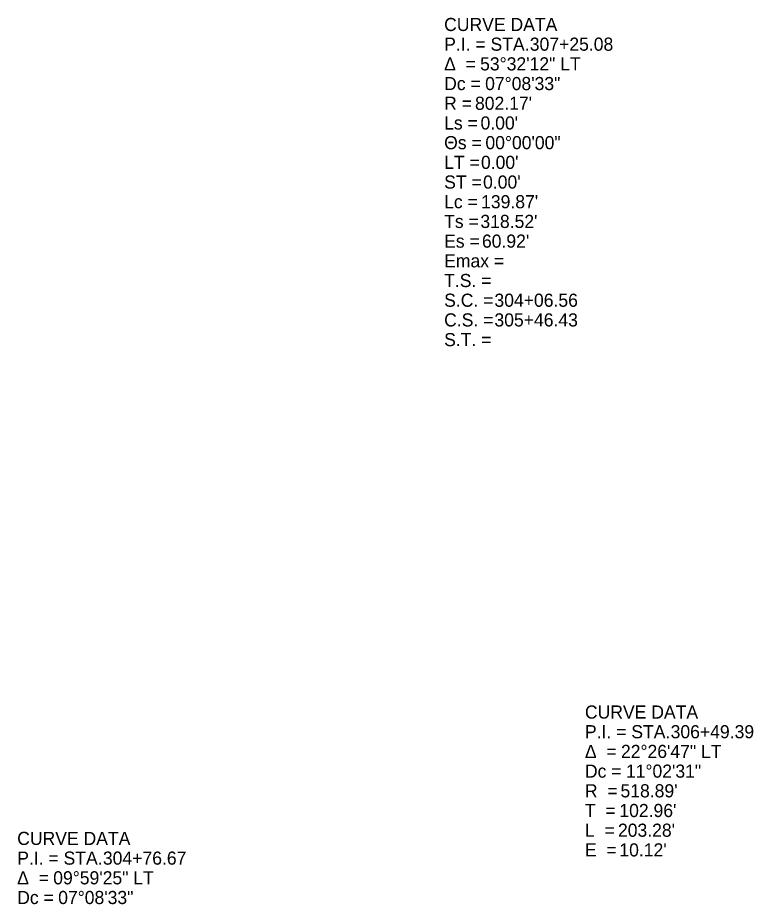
# Model space of a CAD drawing. Extents: x 153902 to 157473, y 413085 to 414252.
# Drawn here: x 154246.5 to 154403.4, y 413877.8 to 414066.9 of the extents above; entities that cross this region are included whole.
import ezdxf

# ---------------------------------------------------------------- set-up
doc = ezdxf.new("R2010")
doc.units = 0
doc.layers.add('GE_P_Alignment_100_Distances', color=7, linetype='Continuous')

msp = doc.modelspace()

# ---------------------------------------------------------------- texts
at = {"layer": 'GE_P_Alignment_100_Distances'}
for s, p in [('CURVE DATA', (154337.45, 414064.06)), ('P.I. = STA. ', (154337.45, 414059.86)), ('307+25.08', (154355.71, 414059.86)), ('Δ  = ', (154337.45, 414055.66)), ('53°32\'12" LT', (154345.12, 414055.66)), ('Dc = ', (154337.45, 414051.46)), ('07°08\'33"', (154346.19, 414051.46)), ('R = ', (154337.45, 414047.26)), ("802.17'", (154344.03, 414047.26)), ('Ls = ', (154337.45, 414043.06)), ("0.00'", (154345.21, 414043.06)), ('Θs = ', (154337.45, 414038.86)), ('00°00\'00"', (154346.25, 414038.86)), ('LT = ', (154337.45, 414034.66)), ("0.00'", (154345.3, 414034.66)), ('ST = ', (154337.45, 414030.46)), ("0.00'", (154345.75, 414030.46)), ('Lc = ', (154337.45, 414026.26)), ("139.87'", (154345.33, 414026.26)), ('Ts = ', (154337.45, 414022.06)), ("318.52'", (154345.18, 414022.06)), ('Es = ', (154337.45, 414017.86)), ("60.92'", (154345.51, 414017.86)), ('Emax = ', (154337.45, 414013.66)), ('T.S. = ', (154337.45, 414009.46)), ('S.C. = ', (154337.45, 414005.26)), ('304+06.56', (154348.17, 414005.26)), ('C.S. = ', (154337.45, 414001.06)), ('305+46.43', (154348.17, 414001.06)), ('S.T. = ', (154337.45, 413996.86)), ('CURVE DATA', (154367.47, 413917.44)), ('P.I. = STA. ', (154367.47, 413913.24)), ('306+49.39', (154385.74, 413913.24)), ('Δ  = ', (154367.47, 413909.04)), ('22°26\'47" LT', (154375.15, 413909.04)), ('Dc = ', (154367.47, 413904.84)), ('11°02\'31"', (154376.21, 413904.84)), ('R  = ', (154367.47, 413900.64)), ("518.89'", (154375.05, 413900.64)), ('T  = ', (154367.47, 413896.44)), ("102.96'", (154374.81, 413896.44)), ('L  = ', (154367.47, 413892.24)), ("203.28'", (154374.51, 413892.24)), ('CURVE DATA', (154246.42, 413890.49)), ('E  = ', (154367.47, 413888.04)), ("10.12'", (154374.81, 413888.04)), ('P.I. = STA. ', (154246.42, 413886.29)), ('304+76.67', (154264.69, 413886.29)), ('Δ  = ', (154246.42, 413882.09)), ('09°59\'25" LT', (154254.1, 413882.09)), ('Dc = ', (154246.42, 413877.89)), ('07°08\'33"', (154255.16, 413877.89))]:
    msp.add_text(s, height=2.8, dxfattribs=at).set_placement(p)

doc.saveas('drawing.dxf')
